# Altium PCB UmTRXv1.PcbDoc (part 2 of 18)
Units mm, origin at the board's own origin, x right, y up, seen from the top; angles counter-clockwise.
Board outline 172 x 113 mm, 6 copper layers (Top Layer, GND, MidLayer1, Mid-Layer 2, InternalPlane2, Bottom Layer); 766 components, 613 nets, 3008 pads, 1360 vias.
Unrouted connection lines stored in the file: 2.
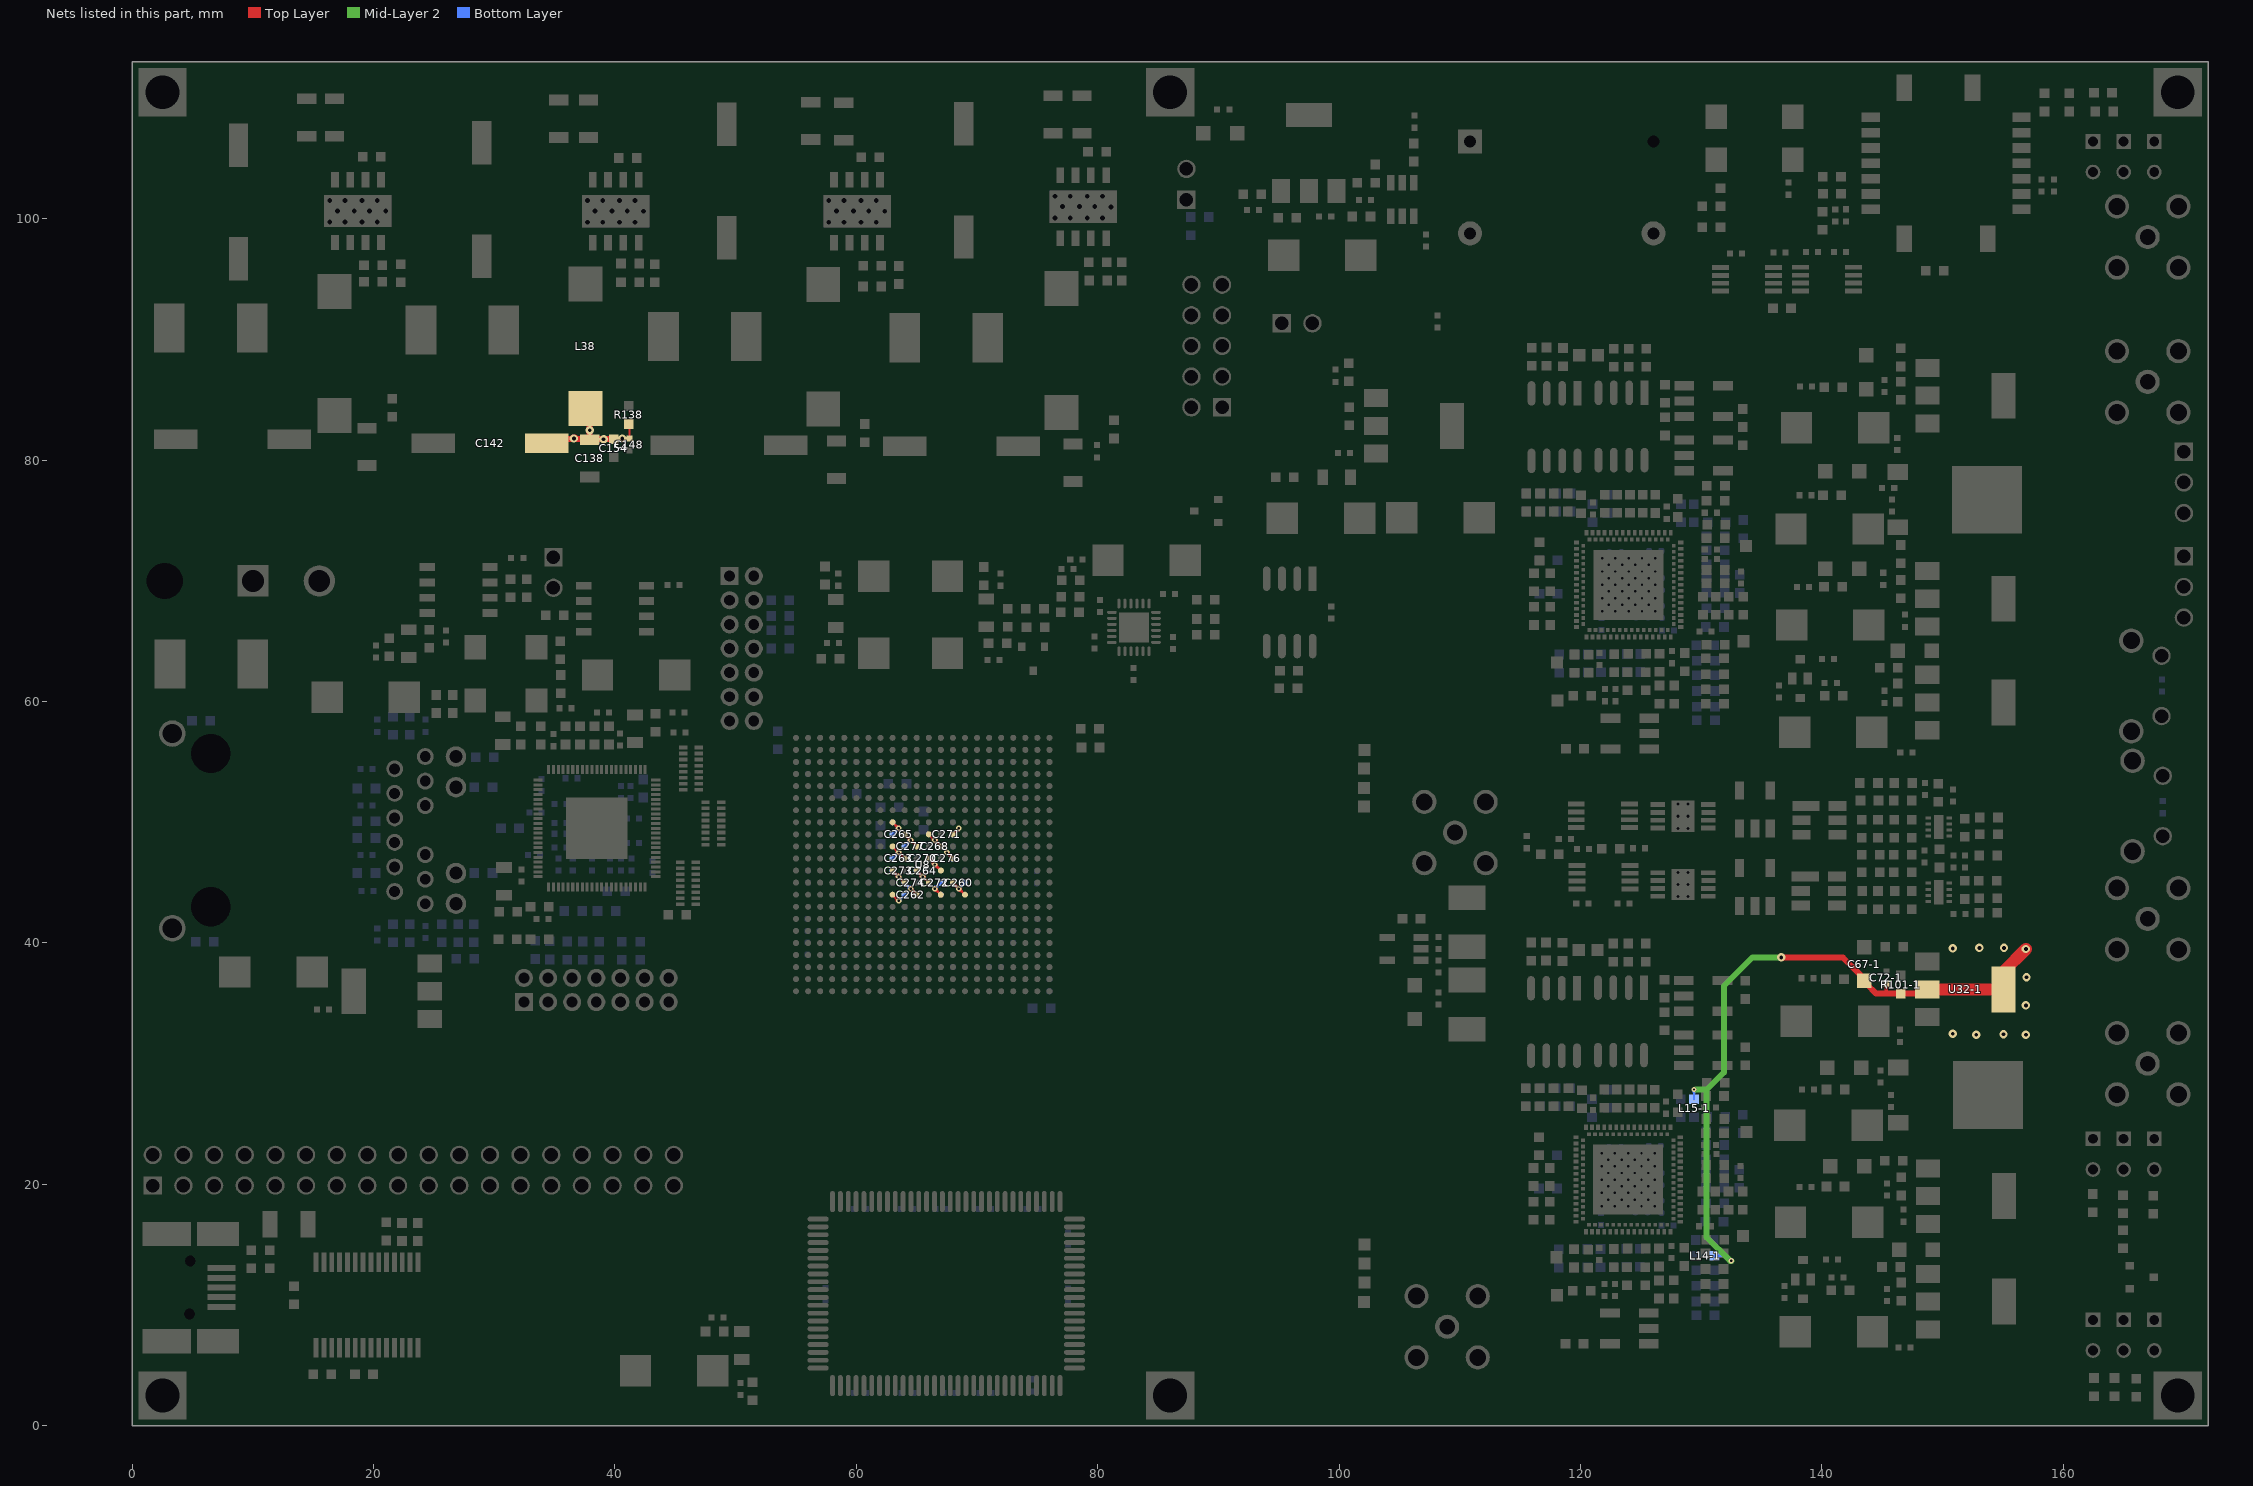
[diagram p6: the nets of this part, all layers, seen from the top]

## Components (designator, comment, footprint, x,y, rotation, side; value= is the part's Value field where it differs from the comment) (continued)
R125-2 "??" R0603-PHILLIPS 124.1,76.4 r270 top (schematic designator R125)
R126-1 "10" R0603-PHILLIPS 115.912,39.283 r90 top (schematic designator R126)
R126-2 "10" R0603-PHILLIPS 115.951,88.575 r90 top (schematic designator R126)
R127-1 "10" R0603-PHILLIPS 125.411,39.208 r90 top (schematic designator R127)
R127-2 "10" R0603-PHILLIPS 125.45,88.5 r90 top (schematic designator R127)
R128 "3k3" R0603-PHILLIPS 61.15,105.1 r0 top
R129 "4k7" R0603-PHILLIPS 19.85,105.15 r0 top
R130 "?" R0603-PHILLIPS 41.05,105.05 r0 top
R131 "4k7" R0603-PHILLIPS 61.3,94.4 r180 top
R132 "4k7" R0603-PHILLIPS 19.95,94.8 r180 top
R133 "4k7" R0603-PHILLIPS 41.25,94.75 r180 top
R134 "120" R0603-PHILLIPS 100.85,83.65 r90 top
R135 "360" R0603-PHILLIPS 100.8,87.3 r90 top
R136 "5k6" R0603-PHILLIPS 60.7,82.25 r90 top
R137 "5k1" R0603-PHILLIPS 21.55,84.35 r90 top
R138 "0" R0603-PHILLIPS 41.15,83.75 r90 top
R139 "430" R0603-PHILLIPS 143.351,43.556 r90 top
R140 "430" R0603-PHILLIPS 143.301,49.456 r90 top
R141 "12" R0603-PHILLIPS 144.651,43.556 r270 top
R142 "12" R0603-PHILLIPS 144.651,49.456 r270 top
R143 "6k8" R0603-PHILLIPS 153.8,43.7 r180 top
R144 "430" R0603-PHILLIPS 146.051,43.556 r270 top
R145 "6k8" R0603-PHILLIPS 153.85,49 r180 top
R146 "430" R0603-PHILLIPS 146.001,49.456 r270 top
R147 "10" R0603-PHILLIPS 146.7,47.3 r180 top
R148 "10" R0603-PHILLIPS 146.751,53.256 r180 top
R149 "330" R0603-PHILLIPS 53.7,64.4 r0 bottom
R150 "??" R0603-PHILLIPS 53.7,67.1 r180 bottom
R151 "??" R0603-PHILLIPS 53.7,65.9 r180 bottom
R152 "2k4" R0603-PHILLIPS 53.7,68.4 r180 bottom
R153 "1k" R0603-PHILLIPS 136.7,92.6 r0 top
R154-1 "270" R0603-PHILLIPS 116.111,17.808 r90 top (schematic designator R154)
R154-2 "270" R0603-PHILLIPS 116.15,67.1 r90 top (schematic designator R154)
R155-1 "62" R0603-PHILLIPS 117.461,17.808 r90 top (schematic designator R155)
R155-2 "62" R0603-PHILLIPS 117.5,67.1 r90 top (schematic designator R155)
R156-1 "62" R0603-PHILLIPS 130.111,18.658 r90 top (schematic designator R156)
R156-2 "62" R0603-PHILLIPS 130.15,67.95 r90 top (schematic designator R156)
R157-1 "270" R0603-PHILLIPS 132.261,18.658 r270 top (schematic designator R157)
R157-2 "270" R0603-PHILLIPS 132.3,67.95 r270 top (schematic designator R157)
R158-1 "270" R0603-PHILLIPS 116.111,20.608 r270 top (schematic designator R158)
R158-2 "270" R0603-PHILLIPS 116.15,69.9 r270 top (schematic designator R158)
R159-1 "62" R0603-PHILLIPS 117.461,20.608 r90 top (schematic designator R159)
R159-2 "62" R0603-PHILLIPS 117.5,69.9 r90 top (schematic designator R159)
R160 "0" R0603-PHILLIPS 88.95,66.85 r0 top
R161 "0" R0603-PHILLIPS 88.95,65.55 r180 top
R162 "330" R0603-PHILLIPS 160.5,109.65 r270 top
R163 "1k" R0603-PHILLIPS 23.65,16.05 r270 top
R164 "1k" R0603-PHILLIPS 21.05,16.1 r270 top
R165 "0" R0603-PHILLIPS 22.35,16.05 r90 top
R166 "0" R0603-PHILLIPS 13.4,10.8 r90 top
R167 "0" R0603-PHILLIPS 88.95,68.45 r0 top
R168 "1k2" R0603-PHILLIPS 79.95,105.575 r0 top
R169 "4k7" R0603-PHILLIPS 80.05,94.9 r180 top
R170 "4k7" R0603-PHILLIPS 81.35,82.55 r90 top
R171 "0" R0603-PHILLIPS 87.7,99.4 r90 bottom
R172 "??" R0603-PHILLIPS 88.45,100.15 r180 bottom
R173 "10k" R0603-PHILLIPS 95.85,62.55 r180 top
R174 "10k" R0603-PHILLIPS 95.8,61.1 r180 top
RA1 "33" YC248 46.3,54.45 r0 top
RA2 "33" YC248 48.15,49.9 r0 top
RA3 "33" YC248 46.05,44.95 r0 top
SW1 "TS-A1PV-130" KNOPKA 168.25,48.85 r90 top
SW2 "TS-A1PV-130" KNOPKA 168.15,58.8 r90 top
SW3 "PLS-3" PLT-3 170,72.04 r270 top
SW4 "PLS-3" PLT-3 170,80.7 r270 top
T1-1 "TC1-1-13MG2" AT224-1 124.061,8.058 r270 top (schematic designator T1)
T1-2 "TC1-1-13MG2" AT224-1 124.1,57.35 r270 top (schematic designator T1)
T2-1 "TC1-1-13MG2" AT224-1 130.161,31.108 r90 top (schematic designator T2)
T2-2 "TC1-1-13MG2" AT224-1 130.2,80.4 r90 top (schematic designator T2)
T3-1 "TC4-25+" AT224-1 130.161,35.608 r90 top (schematic designator T3)
T3-2 "TC4-25+" AT224-1 130.2,84.9 r90 top (schematic designator T3)
T4 "SBTC-2-20L" AT1030 134.45,44.65 r180 top
T5 "SBTC-2-20L" AT1030 134.45,51.05 r180 top
U1 "DAC121S101CIMK" SOT-23-6 105.239,101.6 r180 top
U2 "OHM4048052GG010020-26.0M" DIL14-20X13,2 108.45,96.3 r0 top
U3 "TCD4029-26.0M" TCXO7X5 137.6,108.456 r180 top
U4 "EB-230" EB-230 150.3,104.6 r180 top
U5 "Si5330K-A00226-GM" "QFN-24(4x4/0/5mm) with Pad" 83,66.15 r270 top
U6 "M25P16-VMW6TG" SOIC8 40.006,67.704 r0 top
U7 "24LC024SN" SOIC8 27.042,69.242 r0 top
U8 "XC6SLX75-2FGG484C" FBGA484 65.5,46.5 r180 top locked
U9 "ET1011C2-CI-DT" QFN-84(10X10/0/4MM)WITH_PAD 38.5,49.5 r270 top locked
U10 "FNETHE025" 7x5mm 30.95,62.3 r180 top
U11 "CY7C1354C-166AXI" QFP-10020X14/0.65] 67.45,10.95 r270 top
U12-1 "LMS6002D" DQFN120(9X9/0.5MM) 123.957,20.388 r270 top locked (schematic designator U12)
U12-2 "LMS6002D" DQFN120(9X9/0.5MM) 123.996,69.68 r270 top locked (schematic designator U12)
U13-1 "AD8130ARZ" SO-8 117.811,33.458 r270 top (schematic designator U13)
U13-2 "AD8130ARZ" SO-8 117.85,82.75 r270 top (schematic designator U13)
U14-1 "AD8130ARZ" SO-8 123.361,33.508 r270 top (schematic designator U14)
U14-2 "AD8130ARZ" SO-8 123.4,82.8 r270 top (schematic designator U14)
U15 "L5973AD" "SOIC8 - BackGND - 0.4mm dia" 60.06,100.637 r90 top
U16 "L5973AD" "SOIC8 - BackGND - 0.4mm dia" 18.7,100.65 r90 top
U17 "L5973AD" "SOIC8 - BackGND - 0.4mm dia" 40.06,100.637 r90 top
U18 "LD1117S" SOT-223-1 103.05,85.15 r270 top
U19 "TPS60403DBV" SOT-23-5[3.1x1.8/0.95] 105.398,39.512 r90 top
U20 "SN74LVC2T45DCT" SO-8-MICRO 121.901,45.456 r90 top
U21 "HMC435MS8G" MS8G 128.5,44.85 r270 top
U22 "SN74LVC2T45DCT" SO-8-MICRO 121.851,50.531 r90 top
U23 "HMC435MS8G" MS8G 128.5,50.5 r270 top
U24 "MGA-633P8" SLP2x2 149.7,44.2 r180 top
U25 "MGA-633P8" SLP2x2 149.701,49.606 r180 top
U26 "SN74LVC2T45DCT" SO-8-MICRO 133.808,94.996 r270 top
U27 "SN74LVC2T45DCT" SO-8-MICRO 140.421,95.011 r270 top
U28 "LD1117S" SOT-223-1 95.2,102.3 r0 top
U29-1 "LD1117DT33" to-252 146.35,29.685 r270 top (schematic designator U29)
U29-2 "LD1117DT33" to-252 146.3,79.02 r270 top (schematic designator U29)
U30-1 "LD1117S" SOT-223-1 148.79,12.581 r270 top (schematic designator U30)
U30-2 "LD1117S" SOT-223-1 148.74,62.226 r270 top (schematic designator U30)
U31-1 "LD1117S" SOT-223-1 148.79,21.327 r270 top (schematic designator U31)
U31-2 "LD1117S" SOT-223-1 148.74,70.826 r270 top (schematic designator U31)
U32-1 "LD1117S" SOT-223-1 148.74,38.456 r270 top (schematic designator U32)
U32-2 "LD1117S" SOT-223-1 148.75,87.65 r270 top (schematic designator U32)
U33 "FT232RL" SSOP-28(5.3x10/0.65) 19.45,10 r270 top
U34 "L5973AD" "SOIC8 - BackGND - 0.4mm dia" 78.8,101 r90 top
U35 "MAX6665ASA" SO-8 95.9,67.4 r270 top
X1 "BH2-14" BH2-14 38.45,36.1 r0 top
X2 "BH2-14" BH2-14 50.5,64.4 r270 top
X3 "USB B-M5-SMD" USB/SM0.8-6H5 -0.45,11.45 r180 top
X4 "0826-1XT-23-F" Bel0826-1XT-23F 3.325,49.35 r90 top locked
X5 "MF-2MRA" MF-2MRA 10,70 r0 top
X6 "MCX" RF-MCX 167,98.5 r0 top
X7 "MCX" RF-MCX 167,86.5 r0 top
X8 "MCX" RF-MCX 108.95,8.2 r0 top
X9 "MCX" RF-MCX 167,30 r0 top
X10 "MCX" RF-MCX 167,42 r0 top
X11 "MCX" RF-MCX 109.6,49.15 r0 top
X12 "PLD-36" PLD-36 1.7,19.9 r0 top
X12-1 "TST1" kp40x40 133.461,15.708 r270 top (schematic designator X12)
X12-2 "TST1" kp40x40 133.5,65 r270 top (schematic designator X12)
X13-1 "TST2" kp40x40 133.75,24.35 r90 top (schematic designator X13)
X13-2 "TST2" kp40x40 133.7,72.9 r90 top (schematic designator X13)
X14-1 "TST3" kp40x40 118.061,10.808 r90 top (schematic designator X14)
X14-2 "TST3" kp40x40 118.1,60.1 r90 top (schematic designator X14)
X15-1 "TST4" kp40x40 118.011,13.958 r90 top (schematic designator X15)
X15-2 "TST4" kp40x40 118.05,63.25 r90 top (schematic designator X15)
X16-1 "RX_I" kp40x40 119.861,39.408 r90 top (schematic designator X16)
X16-2 "RX_I" kp40x40 119.9,88.7 r90 top (schematic designator X16)
X17-1 "RX_Q" kp40x40 121.411,39.408 r90 top (schematic designator X17)
X17-2 "RX_Q" kp40x40 121.45,88.7 r90 top (schematic designator X17)
X18 "SEN1" kp40x40 102.049,10.25 r0 top
X19 "SCLK1" kp40x40 102.1,13.45 r0 top
X20 "MOSI1" kp40x40 102.1,11.85 r0 top
X21 "MISO1" kp40x40 102.1,15 r0 top
X22 "SEN2" kp40x40 102.05,51.3 r0 top
X23 "SCLK2" kp40x40 102.05,54.45 r0 top
X24 "MOSI2" kp40x40 102.05,52.85 r0 top
X25 "MISO2" kp40x40 102.1,56 r0 top
X26 "BH-10" BH-10 88.98,89.47 r90 top
X27 "FAN1" WF-2 87.35,101.6 r90 top
X28 "FAN2" WF-2 95.25,91.35 r0 top
Z1-1 "NFM3DPC223R1H3" NFM3DP 138.44,12.131 r270 top (schematic designator Z1)
Z1-2 "NFM3DPC223R1H3" NFM3DP 138.2,61.9 r270 top (schematic designator Z1)
Z2 "SAW UpLink" DCC6C_L 139.751,44.306 r180 top
Z3 "SAW UpLink" DCC6C_L 139.801,50.156 r180 top

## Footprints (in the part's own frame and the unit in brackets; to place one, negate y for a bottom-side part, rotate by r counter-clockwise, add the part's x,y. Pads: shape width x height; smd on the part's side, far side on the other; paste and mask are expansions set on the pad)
7x5mm [mm]
  rect 1.8x2 smd: 1(-2.54,-2.2) 2(2.54,-2.2) 3(2.54,2.2) 4(-2.54,2.2)
  silkscreen extent -3.7,-2.7 3.7,2.7, body extent -3.6,-2.6 3.6,2.6, height 1.55
AT224-1 [mm] "MiniCircuits TC"
  rect 0.76x1.65 smd: 1(-1.27,1.6) 2(0,1.6) 3(1.27,1.6) 4(1.27,-1.6) 6(-1.27,-1.6)
  silkscreen extent -2.2,-1.8 2.2,1.8, body extent -2.1,-1.9 2.1,1.9, height 3.61
AT1030 [mm] "MiniCircuits DBTC"
  rect 0.76x1.5 smd: 1(-1.27,1.575) 2(0,1.575) 3(1.27,1.575) 4(1.27,-1.575) 6(-1.27,-1.575)
  silkscreen extent -2.2,-1.8 2.2,1.8, body extent -2,-1.7 2,1.7, height 3
Bel0826-1XT-23F [mm]
  round 0 hole 3.25 unplated mask+1.7: 0(-6.35,-3.175) 0(6.35,-3.175)
  round 1.4 hole 0.9: 1(-5.08,-18.415) 2(-3.048,-18.415) 3(-1.016,-18.415) 4(1.016,-18.415) 5(3.048,-18.415) 6(5.08,-18.415) 7(-6.096,-20.955) 8(-4.064,-20.955) 9(-2.032,-20.955) 10(2.032,-20.955) 11(4.064,-20.955) 12(6.096,-20.955)
  round 1.7 hole 1.1: 13(-6.096,-23.495) 14(-3.556,-23.495) 15(3.556,-23.495) 16(6.096,-23.495)
  round 2.2 hole 1.6: 17(-8.128,0) 17(8.001,0)
  silkscreen extent -8.51,-26.16 8.51,5.46, body extent -9.94,-25.4 9.93,7.62, height 14.9
BH2-14 [mm] "Molex  87831-1420"
  rect 1.5x1.5 hole 0.9: 1(-6,-1)
  round 1.5 hole 0.9: 2(-6,1) 3(-4,-1) 4(-4,1) 5(-2,-1) 6(-2,1) 7(0,-1) 8(0,1) 9(2,-1) 10(2,1) 11(4,-1) 12(4,1) 13(6,-1) 14(6,1)
  silkscreen extent -11.1,-2.9 11.1,2.9, body extent -8.32,-3.15 8.33,3.15, height 6.45
BH-10 [mil]
  rect 60x60 hole 44: 1(-200,-51.97)
  round 60 hole 44: 2(-200,48.03) 3(-100,-51.97) 4(-100,48.03) 5(0,-51.97) 6(0,48.03) 7(100,-51.97) 8(100,48.03) 9(200,-51.97) 10(200,48.03)
  silkscreen extent -400,-179 402,181, body extent -390,-165 388,181, height 366
C0402-Cirq [mm]
  rrect70% 0.5x0.5 smd: 1(-0.5,0) 2(0.5,0)
  silkscreen extent -0.9,-0.4 0.9,0.4, body extent -0.5,-0.3 0.5,0.3, height 0.2
C0402-cirq [mm]
  rrect70% 0.5x0.5 smd: 1(-0.5,0) 2(0.5,0)
  silkscreen extent -0.9,-0.4 0.9,0.4, body extent -0.5,-0.3 0.5,0.3, height 0.2
C0402-Phillips [mm]
  rect 0.5x0.5 smd: 1(-0.5,0) 2(0.5,0)
  silkscreen extent -0.9,-0.4 0.9,0.4, body extent -0.57,-0.3 0.57,0.3, height 0.55
C0603-PHILLIPS [mm]
  rect 0.8x0.8 smd: 1(-0.75,0) 2(0.75,0)
  silkscreen extent 0,-0.38 0,0.38, body extent -0.86,-0.45 0.85,0.45, height 0.9
C0603-Phillips [mm]
  rect 0.8x0.8 smd: 1(-0.75,0) 2(0.75,0)
  silkscreen extent 0,-0.38 0,0.38, body extent -0.86,-0.45 0.85,0.45, height 0.9
C0805-Phillips [mm]
  rect 0.9x1.3 smd: 1(-1.15,0) 2(1.15,0)
  silkscreen extent -1.91,-0.92 1.91,0.92, body extent -1.32,-0.69 1.23,0.67, height 0.5
c1206 [mm]
  rect 0.9x1.6 smd: 1(-1.55,0) 2(1.55,0)
  silkscreen extent -2.12,-1.12 2.12,1.12, body extent -1.64,-0.89 1.63,0.86, height 0.9
CA3216 [mm] "Конденсатор эл-лит. тип А  по Fillips"
  rect 1.2x1.2 smd: 1(-1.4,0) 2(1.4,0)
  silkscreen extent -2,-1.1 2.2,1.1, body extent -2.35,-0.9 2.45,0.9, height 1.8
CASE-G [mm] "Allu cylinder"
  rect 3.6x1.6 smd: 1(4.7,0) 2(-4.7,0)
  silkscreen extent -5.3,-5.33 5.3,5.33, body extent -5.8,-5.15 5.8,5.15, height 10.21
CB3528 [mm] "Конденсатор тип B по Fillips"
  rect 1.25x2.2 smd: 1(-1.575,0) 2(1.575,0)
  silkscreen extent -2.3,-1.5 2.5,1.5, body extent -1.79,-1.54 1.8,1.54, height 1
cd7343 [mm]
  rect 2.6x2.6 smd: 1(3.2,0) 2(-3.2,0)
  silkscreen extent -3.7,-2.1 3.7,2.2, body extent -3.51,-2.04 3.5,2.03, height 3.1
CR1812 [mil]
  rect 80x120 smd: 1(-80,0) 2(80,0)
  silkscreen extent -130,-70 130,70, body extent -93,-67 93,67, height 61
DCC6C_L [mm] "SAW"
  rect 2.25x0.8 smd mask+0.1: 1(1.125,-1.2)
  rect 1.5x0.8 smd mask+0.1: 2(1.5,0) 3(1.5,1.2)
  rect 1.5x0.8 smd: 4(-1.5,1.2) 5(-1.5,0) 6(-1.5,-1.2)
  silkscreen extent -2,-2.4 2.3,2, body extent -1.5,-1.5 1.5,1.5, height 1.1
DIL14-20X13,2 [mm] "VCXO"
  rect 2x2 hole 1: 1(2.4,10.1)
  round 0 / inner round 0 / far side round 2 hole 1: 7(17.6,10.1)
  round 2 hole 1: 8(17.6,2.5) 14(2.4,2.5)
  Multi-Layer pour cut-out: 16.8,2.9 17.2,3.3 18,3.3 18.4,2.9 18.4,2.1 18,1.7 17.2,1.7 16.8,2.1
  Multi-Layer pour cut-out: 1.6,2.9 2,3.3 2.8,3.3 3.2,2.9 3.2,2.1 2.8,1.7 2,1.7 1.6,2.1
  Multi-Layer pour cut-out: 1.6,10.5 2,10.9 2.8,10.9 3.2,10.5 3.2,9.7 2.8,9.3 2,9.3 1.6,9.7
  Multi-Layer pour cut-out: 16.8,10.5 17.2,10.9 18,10.9 18.4,10.5 18.4,9.7 18,9.3 17.2,9.3 16.8,9.7
  silkscreen extent -0.25,-0.38 20.32,12.95, body extent 0.07,0.1 20.07,12.7, height 8.2
DQFN120(9X9/0.5MM) [mm] "LMS6002"
  round 0.5 hole 0.2 paste-0.4: 0(-2.2,1.1) 0(-2.2,2.2) 0(-2.2,0) 0(-2.2,-2.2) 0(-2.2,-1.1) 0(-1.65,1.65) 0(-1.65,-0.55) 0(-1.65,0.55) 0(-1.65,-1.65) 0(-1.1,2.2) 0(-1.1,1.1) 0(-1.1,0) 0(-1.1,-1.1) 0(-1.1,-2.2) 0(-0.55,1.65) 0(-0.55,0.55) 0(-0.55,-0.55) 0(-0.55,-1.65) 0(0,2.2) 0(0,1.1) 0(0,0) 0(0,-1.1) 0(0,-2.2) 0(0.55,1.65) 0(0.55,0.55) 0(0.55,-0.55) 0(0.55,-1.65) 0(1.1,2.2) 0(1.1,1.1) 0(1.1,0) 0(1.1,-1.1) 0(1.1,-2.2) 0(1.65,1.65) 0(1.65,-0.55) 0(1.65,0.55) 0(1.65,-1.65) 0(2.2,1.1) 0(2.2,2.2) 0(2.2,0) 0(2.2,-2.2) 0(2.2,-1.1)
  rect 5.8x5.8 smd paste-3: 0(0,0)
  rect 0.3x0.45 smd mask+0.05: 1(-3.5,-4.325) 3(-3,-4.325) 5(-2.5,-4.325) 7(-2,-4.325) 9(-1.5,-4.325) 11(-1,-4.325) 13(-0.5,-4.325) 15(0,-4.325) 17(0.5,-4.325) 19(1,-4.325) 21(1.5,-4.325) 23(2,-4.325) 25(2.5,-4.325) 27(3,-4.325) 29(3.5,-4.325) 59(3.5,4.325) 61(3,4.325) 63(2.5,4.325) 65(2,4.325) 67(1.5,4.325) 69(1,4.325) 71(0.5,4.325) 73(0,4.325) 75(-0.5,4.325) 77(-1,4.325) 79(-1.5,4.325) 81(-2,4.325) 83(-2.5,4.325) 85(-3,4.325) 87(-3.5,4.325)
  rect 0.3x0.3 smd mask+0.05: 2(-3.25,-3.75) 4(-2.75,-3.75) 6(-2.25,-3.75) 8(-1.75,-3.75) 10(-1.25,-3.75) 12(-0.75,-3.75) 14(-0.25,-3.75) 16(0.25,-3.75) 18(0.75,-3.75) 20(1.25,-3.75) 22(1.75,-3.75) 24(2.25,-3.75) 26(2.75,-3.75) 28(3.25,-3.75) 31(3.75,-3.25) 33(3.75,-2.75) 35(3.75,-2.25) 37(3.75,-1.75) 39(3.75,-1.25) 41(3.75,-0.75) 43(3.75,-0.25) 45(3.75,0.25) 47(3.75,0.75) 49(3.75,1.25) 51(3.75,1.75) 53(3.75,2.25) 55(3.75,2.75) 57(3.75,3.25) 60(3.25,3.75) 62(2.75,3.75) 64(2.25,3.75) 66(1.75,3.75) 68(1.25,3.75) 70(0.75,3.75) 72(0.25,3.75) 74(-0.25,3.75) 76(-0.75,3.75) 78(-1.25,3.75) 80(-1.75,3.75) 82(-2.25,3.75) 84(-2.75,3.75) 86(-3.25,3.75) 89(-3.75,3.25) 91(-3.75,2.75) 93(-3.75,2.25) 95(-3.75,1.75) 97(-3.75,1.25) 99(-3.75,0.75) 101(-3.75,0.25) 103(-3.75,-0.25) 105(-3.75,-0.75) 107(-3.75,-1.25) 109(-3.75,-1.75) 111(-3.75,-2.25) 113(-3.75,-2.75) 115(-3.75,-3.25)
  rect 0.45x0.3 smd mask+0.05: 30(4.325,-3.5) 32(4.325,-3) 34(4.325,-2.5) 36(4.325,-2) 38(4.325,-1.5) 40(4.325,-1) 42(4.325,-0.5) 44(4.325,0) 46(4.325,0.5) 48(4.325,1) 50(4.325,1.5) 52(4.325,2) 54(4.325,2.5) 56(4.325,3) 58(4.325,3.5) 88(-4.325,3.5) 90(-4.325,3) 92(-4.325,2.5) 94(-4.325,2) 96(-4.325,1.5) 98(-4.325,1) 100(-4.325,0.5) 102(-4.325,0) 104(-4.325,-0.5) 106(-4.325,-1) 108(-4.325,-1.5) 110(-4.325,-2) 112(-4.325,-2.5) 114(-4.325,-3) 116(-4.325,-3.5)
  silkscreen extent -4.8,-4.8 4.8,4.8, body extent -4.5,-4.5 4.5,4.5, height 0.85
DS3316 [mm] "Coilcraft"
  rect 2.9x2.8 smd: 1(-5.15,0) 2(5.15,0)
  silkscreen extent -5.2,-4.8 5.2,4.8, body extent -4.9,-4.9 5.1,5.1, height 2.8
EB-230 [mm]
  rect 1.5x0.8 smd mask+0.077: 1(-6.25,3.81) 2(-6.25,2.54) 3(-6.25,1.27) 4(-6.25,0) 5(-6.25,-1.27) 6(-6.25,-2.54) 7(-6.25,-3.81) 10(6.25,-3.81) 11(6.25,-2.54) 12(6.25,-1.27) 13(6.25,0) 14(6.25,1.27) 15(6.25,2.54) 16(6.25,3.81)
  rect 1.3x2.2 smd mask+0.077: 8(-2.19,-6.25) 9(3.46,-6.25) 17(3.46,6.25) 18(-3.46,6.25)
  silkscreen extent -6.4,-6.4 6.4,6.4, body extent -6.25,-6.25 6,6.25, height 2.9
FBGA484 [mm] "BGA, 484-Leads, Body 23x23mm, Pitch 1mm"
  round 0.5 smd: A1(-10.5,10.5) A2(-9.5,10.5) A3(-8.5,10.5) A4(-7.5,10.5) A5(-6.5,10.5) A6(-5.5,10.5) A7(-4.5,10.5) A8(-3.5,10.5) A9(-2.5,10.5) A10(-1.5,10.5) A11(-0.5,10.5) A12(0.5,10.5) A13(1.5,10.5) A14(2.5,10.5) A15(3.5,10.5) A16(4.5,10.5) A17(5.5,10.5) A18(6.5,10.5) A19(7.5,10.5) A20(8.5,10.5) A21(9.5,10.5) A22(10.5,10.5) AA1(-10.5,-9.5) AA2(-9.5,-9.5) AA3(-8.5,-9.5) AA4(-7.5,-9.5) AA5(-6.5,-9.5) AA6(-5.5,-9.5) AA7(-4.5,-9.5) AA8(-3.5,-9.5) AA9(-2.5,-9.5) AA10(-1.5,-9.5) AA11(-0.5,-9.5) AA12(0.5,-9.5) AA13(1.5,-9.5) AA14(2.5,-9.5) AA15(3.5,-9.5) AA16(4.5,-9.5) AA17(5.5,-9.5) AA18(6.5,-9.5) AA19(7.5,-9.5) AA20(8.5,-9.5) AA21(9.5,-9.5) AA22(10.5,-9.5) AB1(-10.5,-10.5) AB2(-9.5,-10.5) AB3(-8.5,-10.5) AB4(-7.5,-10.5) AB5(-6.5,-10.5) AB6(-5.5,-10.5) AB7(-4.5,-10.5) AB8(-3.5,-10.5) AB9(-2.5,-10.5) AB10(-1.5,-10.5) AB11(-0.5,-10.5) AB12(0.5,-10.5) AB13(1.5,-10.5) AB14(2.5,-10.5) AB15(3.5,-10.5) AB16(4.5,-10.5) AB17(5.5,-10.5) AB18(6.5,-10.5) AB19(7.5,-10.5) AB20(8.5,-10.5) AB21(9.5,-10.5) AB22(10.5,-10.5) B1(-10.5,9.5) B2(-9.5,9.5) B3(-8.5,9.5) B4(-7.5,9.5) B5(-6.5,9.5) B6(-5.5,9.5) B7(-4.5,9.5) B8(-3.5,9.5) B9(-2.5,9.5) B10(-1.5,9.5) B11(-0.5,9.5) B12(0.5,9.5) B13(1.5,9.5) B14(2.5,9.5) B15(3.5,9.5) B16(4.5,9.5) B17(5.5,9.5) B18(6.5,9.5) B19(7.5,9.5) B20(8.5,9.5) B21(9.5,9.5) B22(10.5,9.5) C1(-10.5,8.5) C2(-9.5,8.5) C3(-8.5,8.5) C4(-7.5,8.5) C5(-6.5,8.5) C6(-5.5,8.5) C7(-4.5,8.5) C8(-3.5,8.5) C9(-2.5,8.5) C10(-1.5,8.5) C11(-0.5,8.5) C12(0.5,8.5) C13(1.5,8.5) C14(2.5,8.5) C15(3.5,8.5) C16(4.5,8.5) C17(5.5,8.5) C18(6.5,8.5) C19(7.5,8.5) C20(8.5,8.5) C21(9.5,8.5) C22(10.5,8.5) D1(-10.5,7.5) D2(-9.5,7.5) D3(-8.5,7.5) D4(-7.5,7.5) D5(-6.5,7.5) D6(-5.5,7.5) D7(-4.5,7.5) D8(-3.5,7.5) D9(-2.5,7.5) D10(-1.5,7.5) D11(-0.5,7.5) D12(0.5,7.5) D13(1.5,7.5) D14(2.5,7.5) D15(3.5,7.5) D16(4.5,7.5) D17(5.5,7.5) D18(6.5,7.5) D19(7.5,7.5) D20(8.5,7.5) D21(9.5,7.5) D22(10.5,7.5) E1(-10.5,6.5) E2(-9.5,6.5) E3(-8.5,6.5) E4(-7.5,6.5) E5(-6.5,6.5) E6(-5.5,6.5) E7(-4.5,6.5) E8(-3.5,6.5) E9(-2.5,6.5) E10(-1.5,6.5) E11(-0.5,6.5) E12(0.5,6.5) E13(1.5,6.5) E14(2.5,6.5) E15(3.5,6.5) E16(4.5,6.5) E17(5.5,6.5) E18(6.5,6.5) E19(7.5,6.5) E20(8.5,6.5) E21(9.5,6.5) E22(10.5,6.5) F1(-10.5,5.5) F2(-9.5,5.5) F3(-8.5,5.5) F4(-7.5,5.5) F5(-6.5,5.5) F6(-5.5,5.5) F7(-4.5,5.5) F8(-3.5,5.5) F9(-2.5,5.5) F10(-1.5,5.5) F11(-0.5,5.5) F12(0.5,5.5) F13(1.5,5.5) F14(2.5,5.5) F15(3.5,5.5) F16(4.5,5.5) F17(5.5,5.5) F18(6.5,5.5) F19(7.5,5.5) F20(8.5,5.5) F21(9.5,5.5) F22(10.5,5.5) G1(-10.5,4.5) G2(-9.5,4.5) G3(-8.5,4.5) G4(-7.5,4.5) G5(-6.5,4.5) G6(-5.5,4.5) G7(-4.5,4.5) G8(-3.5,4.5) G9(-2.5,4.5) G10(-1.5,4.5) G11(-0.5,4.5) G12(0.5,4.5) G13(1.5,4.5) G14(2.5,4.5) G15(3.5,4.5) G16(4.5,4.5) G17(5.5,4.5) G18(6.5,4.5) G19(7.5,4.5) G20(8.5,4.5) G21(9.5,4.5) G22(10.5,4.5) H1(-10.5,3.5) H2(-9.5,3.5) H3(-8.5,3.5) H4(-7.5,3.5) H5(-6.5,3.5) H6(-5.5,3.5) H7(-4.5,3.5) H8(-3.5,3.5) H9(-2.5,3.5) H10(-1.5,3.5) H11(-0.5,3.5) H12(0.5,3.5) H13(1.5,3.5) H14(2.5,3.5) H15(3.5,3.5) H16(4.5,3.5) H17(5.5,3.5) H18(6.5,3.5) H19(7.5,3.5) H20(8.5,3.5) H21(9.5,3.5) H22(10.5,3.5) J1(-10.5,2.5) J2(-9.5,2.5) J3(-8.5,2.5) J4(-7.5,2.5) J5(-6.5,2.5) J6(-5.5,2.5) J7(-4.5,2.5) J8(-3.5,2.5) J9(-2.5,2.5) J10(-1.5,2.5) J11(-0.5,2.5) J12(0.5,2.5) J13(1.5,2.5) J14(2.5,2.5) J15(3.5,2.5) J16(4.5,2.5) J17(5.5,2.5) J18(6.5,2.5) J19(7.5,2.5) J20(8.5,2.5) J21(9.5,2.5) J22(10.5,2.5) K1(-10.5,1.5) K2(-9.5,1.5) K3(-8.5,1.5) K4(-7.5,1.5) K5(-6.5,1.5) K6(-5.5,1.5) K7(-4.5,1.5) K8(-3.5,1.5) K9(-2.5,1.5) K10(-1.5,1.5) K11(-0.5,1.5) K12(0.5,1.5) K13(1.5,1.5) K14(2.5,1.5) K15(3.5,1.5) K16(4.5,1.5) K17(5.5,1.5) K18(6.5,1.5) K19(7.5,1.5) K20(8.5,1.5) K21(9.5,1.5) K22(10.5,1.5) L1(-10.5,0.5) L2(-9.5,0.5) L3(-8.5,0.5) L4(-7.5,0.5) L5(-6.5,0.5) L6(-5.5,0.5) L7(-4.5,0.5) L8(-3.5,0.5) L9(-2.5,0.5) L10(-1.5,0.5) L11(-0.5,0.5) L12(0.5,0.5) L13(1.5,0.5) L14(2.5,0.5) L15(3.5,0.5) L16(4.5,0.5) L17(5.5,0.5) L18(6.5,0.5) L19(7.5,0.5) L20(8.5,0.5) L21(9.5,0.5) L22(10.5,0.5) M1(-10.5,-0.5) M2(-9.5,-0.5) M3(-8.5,-0.5) M4(-7.5,-0.5) M5(-6.5,-0.5) M6(-5.5,-0.5) M7(-4.5,-0.5) M8(-3.5,-0.5) M9(-2.5,-0.5) M10(-1.5,-0.5) M11(-0.5,-0.5) M12(0.5,-0.5) M13(1.5,-0.5) M14(2.5,-0.5) M15(3.5,-0.5) M16(4.5,-0.5) M17(5.5,-0.5) M18(6.5,-0.5) M19(7.5,-0.5) M20(8.5,-0.5) M21(9.5,-0.5) M22(10.5,-0.5) N1(-10.5,-1.5) N2(-9.5,-1.5) N3(-8.5,-1.5) N4(-7.5,-1.5) N5(-6.5,-1.5) N6(-5.5,-1.5) N7(-4.5,-1.5) N8(-3.5,-1.5) N9(-2.5,-1.5) N10(-1.5,-1.5) N11(-0.5,-1.5) N12(0.5,-1.5) N13(1.5,-1.5) N14(2.5,-1.5) N15(3.5,-1.5) N16(4.5,-1.5) N17(5.5,-1.5) N18(6.5,-1.5) N19(7.5,-1.5) N20(8.5,-1.5) N21(9.5,-1.5) N22(10.5,-1.5) P1(-10.5,-2.5) P2(-9.5,-2.5) P3(-8.5,-2.5) P4(-7.5,-2.5) P5(-6.5,-2.5) P6(-5.5,-2.5) P7(-4.5,-2.5) P8(-3.5,-2.5) P9(-2.5,-2.5) P10(-1.5,-2.5) P11(-0.5,-2.5) P12(0.5,-2.5) P13(1.5,-2.5) P14(2.5,-2.5) P15(3.5,-2.5) P16(4.5,-2.5) P17(5.5,-2.5) P18(6.5,-2.5) P19(7.5,-2.5) P20(8.5,-2.5) P21(9.5,-2.5) P22(10.5,-2.5) R1(-10.5,-3.5) R2(-9.5,-3.5) R3(-8.5,-3.5) R4(-7.5,-3.5) R5(-6.5,-3.5) R6(-5.5,-3.5) R7(-4.5,-3.5) R8(-3.5,-3.5) R9(-2.5,-3.5) R10(-1.5,-3.5) R11(-0.5,-3.5) R12(0.5,-3.5) R13(1.5,-3.5) R14(2.5,-3.5) R15(3.5,-3.5) R16(4.5,-3.5) R17(5.5,-3.5) R18(6.5,-3.5) R19(7.5,-3.5) R20(8.5,-3.5) R21(9.5,-3.5) R22(10.5,-3.5) T1(-10.5,-4.5) T2(-9.5,-4.5) T3(-8.5,-4.5) T4(-7.5,-4.5) T5(-6.5,-4.5) T6(-5.5,-4.5) T7(-4.5,-4.5) T8(-3.5,-4.5) T9(-2.5,-4.5) T10(-1.5,-4.5) T11(-0.5,-4.5) T12(0.5,-4.5) T13(1.5,-4.5) T14(2.5,-4.5) T15(3.5,-4.5) T16(4.5,-4.5) T17(5.5,-4.5) T18(6.5,-4.5) T19(7.5,-4.5) T20(8.5,-4.5) T21(9.5,-4.5) T22(10.5,-4.5) U1(-10.5,-5.5) U2(-9.5,-5.5) U3(-8.5,-5.5) U4(-7.5,-5.5) U5(-6.5,-5.5) U6(-5.5,-5.5) U7(-4.5,-5.5) U8(-3.5,-5.5) U9(-2.5,-5.5) U10(-1.5,-5.5) U11(-0.5,-5.5) U12(0.5,-5.5) U13(1.5,-5.5) U14(2.5,-5.5) U15(3.5,-5.5) U16(4.5,-5.5) U17(5.5,-5.5) U18(6.5,-5.5) U19(7.5,-5.5) U20(8.5,-5.5) U21(9.5,-5.5) U22(10.5,-5.5) V1(-10.5,-6.5) V2(-9.5,-6.5) V3(-8.5,-6.5) V4(-7.5,-6.5) V5(-6.5,-6.5) V6(-5.5,-6.5) V7(-4.5,-6.5) V8(-3.5,-6.5) V9(-2.5,-6.5) V10(-1.5,-6.5) V11(-0.5,-6.5) V12(0.5,-6.5) V13(1.5,-6.5) V14(2.5,-6.5) V15(3.5,-6.5) V16(4.5,-6.5) V17(5.5,-6.5) V18(6.5,-6.5) V19(7.5,-6.5) V20(8.5,-6.5) V21(9.5,-6.5) V22(10.5,-6.5) W1(-10.5,-7.5) W2(-9.5,-7.5) W3(-8.5,-7.5) W4(-7.5,-7.5) W5(-6.5,-7.5) W6(-5.5,-7.5) W7(-4.5,-7.5) W8(-3.5,-7.5) W9(-2.5,-7.5) W10(-1.5,-7.5) W11(-0.5,-7.5) W12(0.5,-7.5) W13(1.5,-7.5) W14(2.5,-7.5) W15(3.5,-7.5) W16(4.5,-7.5) W17(5.5,-7.5) W18(6.5,-7.5) W19(7.5,-7.5) W20(8.5,-7.5) W21(9.5,-7.5) W22(10.5,-7.5) Y1(-10.5,-8.5) Y2(-9.5,-8.5) Y3(-8.5,-8.5) Y4(-7.5,-8.5) Y5(-6.5,-8.5) Y6(-5.5,-8.5) Y7(-4.5,-8.5) Y8(-3.5,-8.5) Y9(-2.5,-8.5) Y10(-1.5,-8.5) Y11(-0.5,-8.5) Y12(0.5,-8.5) Y13(1.5,-8.5) Y14(2.5,-8.5) Y15(3.5,-8.5) Y16(4.5,-8.5) Y17(5.5,-8.5) Y18(6.5,-8.5) Y19(7.5,-8.5) Y20(8.5,-8.5) Y21(9.5,-8.5) Y22(10.5,-8.5)
  silkscreen extent -12.27,-11.5 11.5,11.5, body extent -11.5,-11.5 11.5,11.5, height 3.5
KNOPKA [mil]
  round 60 hole 44: 1(0,0) 2(196.85,0)
  round 80 hole 56: 3(-49.21,98.43) 4(246.07,98.43)
  silkscreen extent -52,-115 248,175, body extent -62,-153 259,154, height 280
kp40x40 [mm]
  rect 1x1 smd: 1(0,0)
L-7104SA/3 [mil] "L-7104SA/3"
  rect 48x48 hole 32: 1(-50,-175.2) 2(-50,-275.2) 3(-50,-375.2)
  round 48 hole 32: 4(50,-375.2) 5(50,-275.2) 6(50,-175.2)
  silkscreen extent -104,-455 104,0, body extent -100,-451 100,103, height 600
LED-0603y [mm] "жёлтый"
  rect 0.8x0.8 smd: 1(-0.75,0) 2(0.75,0)
  silkscreen extent -1.45,-0.6 0.8,0.6, body extent -1.09,-0.4 0.92,0.4, height 0.8
MF-2MRA [mm]
  round 0 hole 3 unplated mask+1.6: 0(-7.3,0)
  rect 2.6x2.6 hole 1.8: 1(0,0)
  round 2.6 hole 1.8: 2(5.5,0)
  silkscreen extent -14,-2.8 -1,2.8, body extent -13.86,-3.13 6.08,2.67, height 11.4
MS8G [mm] "Hittite 8 Leg Grounded microSOIC"
  round 0.5 hole 0.254 paste-0.125 mask-0.125: 0(-1,-0.4) 0(-1,0.4) 0(0,0.4) 0(0,-0.4) 0(1,-0.4) 0(1,0.4)
  rect 2.6x1.9 smd paste-1.5: 0(0,0)
  rect 0.4x1.2 smd mask+0.075: 1(-0.975,-2.1) 2(-0.325,-2.1) 3(0.325,-2.1) 4(0.975,-2.1) 5(0.975,2.1) 6(0.325,2.1) 7(-0.325,2.11) 8(-0.975,2.1)
  silkscreen extent -1.65,-1.65 1.65,1.65, body extent -1.5,-2.45 1.5,2.45, height 0.85
NFM3DP [mm] "Фильтр электромагнитных помех"
  rect 0.7x0.8 smd: 1(-1.6,0) 3(1.6,0)
  rect 1x0.7 smd: 2(0,0.65) 2(0,-0.65)
  silkscreen extent -2,-1.3 2.1,1.3, body extent -1.6,-0.7 1.6,0.7, height 0.55
PLD-36 [mil]
  rect 60x60 hole 44: 1(0,0)
  round 60 hole 44: 2(0,100) 3(100,0) 4(100,100) 5(200,0) 6(200,100) 7(300,0) 8(300,100) 9(400,0) 10(400,100) 11(500,0) 12(500,100) 13(600,0) 14(600,100) 15(700,0) 16(700,100) 17(800,0) 18(800,100) 19(900,0) 20(900,100) 21(1000,0) 22(1000,100) 23(1100,0) 24(1100,100) 25(1200,0) 26(1200,100) 27(1300,0) 28(1300,100) 29(1400,0) 30(1400,100) 31(1500,0) 32(1500,100) 33(1600,0) 34(1600,100) 35(1700,0) 36(1700,100)
  silkscreen extent -50,-50 1750,150, body extent -50,-50 1750,150, height 398
PLT-2 [mil]
  rect 60x60 / inner round 60 / far side rect 60x60 hole 44: 1(-50,0)
  round 60 hole 44: 2(50,0)
  silkscreen extent -100,-50 100,50, body extent -90,-38 87,40, height 276
PLT-3 [mil]
  rect 60x60 hole 44: 1(0,0)
  round 60 hole 44: 2(100,0) 3(200,0)
  silkscreen extent -50,-50 250,50, body extent -50,-52 250,46, height 410
"QFN-24(4x4/0/5mm) with Pad" [mm] "PQFN"
  rect 2.5x2.5 smd paste-2: 0(0,0)
  oval 0.8x0.25 smd mask+0.075: 1(-1.975,1.25) 2(-1.975,0.75) 3(-1.975,0.25) 4(-1.975,-0.25) 5(-1.975,-0.75) 6(-1.975,-1.25) 13(1.975,-1.25) 14(1.975,-0.75) 15(1.975,-0.25) 16(1.975,0.25) 17(1.975,0.75) 18(1.975,1.25)
  oval 0.25x0.8 smd mask+0.075: 7(-1.25,-1.825) 8(-0.75,-1.825) 9(-0.25,-1.825) 10(0.25,-1.825) 11(0.75,-1.825) 12(1.25,-1.825) 19(1.25,1.825) 20(0.75,1.825) 21(0.25,1.825) 22(-0.25,1.825) 23(-0.75,1.825) 24(-1.25,1.825)
  silkscreen extent -2.97,-2.1 2.1,2.1, body extent -2.1,-1.92 2.1,1.92, height 0.9
QFN-84(10X10/0/4MM)WITH_PAD [mm] "QFN, 84-Leads, Body 10,0x10,0mm (max), Pitch 0,40mm, IPC High Density"
  rect 5.1x5.1 smd paste-3: 0(0,0)
  rect 0.75x0.25 smd: 1(-4.875,4) 2(-4.875,3.6) 3(-4.875,3.2) 4(-4.875,2.8) 5(-4.875,2.4) 6(-4.875,2) 7(-4.875,1.6) 8(-4.875,1.2) 9(-4.875,0.8) 10(-4.875,0.4) 11(-4.875,0) 12(-4.875,-0.4) 13(-4.875,-0.8) 14(-4.875,-1.2) 15(-4.875,-1.6) 16(-4.875,-2) 17(-4.875,-2.4) 18(-4.875,-2.8) 19(-4.875,-3.2) 20(-4.875,-3.6) 21(-4.875,-4) 43(4.875,-4) 44(4.875,-3.6) 45(4.875,-3.2) 46(4.875,-2.8) 47(4.875,-2.4) 48(4.875,-2) 49(4.875,-1.6) 50(4.875,-1.2) 51(4.875,-0.8) 52(4.875,-0.4) 53(4.875,0) 54(4.875,0.4) 55(4.875,0.8) 56(4.875,1.2) 57(4.875,1.6) 58(4.875,2) 59(4.875,2.4) 60(4.875,2.8) 61(4.875,3.2) 62(4.875,3.6) 63(4.875,4)
  rect 0.25x0.75 smd: 22(-4,-4.875) 23(-3.6,-4.875) 24(-3.2,-4.875) 25(-2.8,-4.875) 26(-2.4,-4.875) 27(-2,-4.875) 28(-1.6,-4.875) 29(-1.2,-4.875) 30(-0.8,-4.875) 31(-0.4,-4.875) 32(0,-4.875) 33(0.4,-4.875) 34(0.8,-4.875) 35(1.2,-4.875) 36(1.6,-4.875) 37(2,-4.875) 38(2.4,-4.875) 39(2.8,-4.875) 40(3.2,-4.875) 41(3.6,-4.875) 42(4,-4.875) 64(4,4.875) 65(3.6,4.875) 66(3.2,4.875) 67(2.8,4.875) 68(2.4,4.875) 69(2,4.875) 70(1.6,4.875) 71(1.2,4.875) 72(0.8,4.875) 73(0.4,4.875) 74(0,4.875) 75(-0.4,4.875) 76(-0.8,4.875) 77(-1.2,4.875) 78(-1.6,4.875) 79(-2,4.875) 80(-2.4,4.875) 81(-2.8,4.875) 82(-3.2,4.875) 83(-3.6,4.875) 84(-4,4.875)
  silkscreen extent -5.92,-5 5,5, body extent -5,-5 5,5, height 0.85
QFP-10020X14/0.65] [mm] "Thin QFP, 100-Leads, Body 20x14mm, Pitch 0.65mm, IPC Medium Density"
  oval 1.75x0.4 smd mask+0.075: 1(-7.625,9.425) 2(-7.625,8.775) 3(-7.625,8.125) 4(-7.625,7.475) 5(-7.625,6.825) 6(-7.625,6.175) 7(-7.625,5.525) 8(-7.625,4.875) 9(-7.625,4.225) 10(-7.625,3.575) 11(-7.625,2.925) 12(-7.625,2.275) 13(-7.625,1.625) 14(-7.625,0.975) 15(-7.625,0.325) 16(-7.625,-0.325) 17(-7.625,-0.975) 18(-7.625,-1.625) 19(-7.625,-2.275) 20(-7.625,-2.925) 21(-7.625,-3.575) 22(-7.625,-4.225) 23(-7.625,-4.875) 24(-7.625,-5.525) 25(-7.625,-6.175) 26(-7.625,-6.825) 27(-7.625,-7.475) 28(-7.625,-8.125) 29(-7.625,-8.775) 30(-7.625,-9.425) 51(7.625,-9.425) 52(7.625,-8.775) 53(7.625,-8.125) 54(7.625,-7.475) 55(7.625,-6.825) 56(7.625,-6.175) 57(7.625,-5.525) 58(7.625,-4.875) 59(7.625,-4.225) 60(7.625,-3.575) 61(7.625,-2.925) 62(7.625,-2.275) 63(7.625,-1.625) 64(7.625,-0.975) 65(7.625,-0.325) 66(7.625,0.325) 67(7.625,0.975) 68(7.625,1.625) 69(7.625,2.275) 70(7.625,2.925) 71(7.625,3.575) 72(7.625,4.225) 73(7.625,4.875) 74(7.625,5.525) 75(7.625,6.175) 76(7.625,6.825) 77(7.625,7.475) 78(7.625,8.125) 79(7.625,8.775) 80(7.625,9.425)
  oval 0.4x1.75 smd mask+0.075: 31(-6.175,-10.625) 32(-5.525,-10.625) 33(-4.875,-10.625) 34(-4.225,-10.625) 35(-3.575,-10.625) 36(-2.925,-10.625) 37(-2.275,-10.625) 38(-1.625,-10.625) 39(-0.975,-10.625) 40(-0.325,-10.625) 41(0.325,-10.625) 42(0.975,-10.625) 43(1.625,-10.625) 44(2.275,-10.625) 45(2.925,-10.625) 46(3.575,-10.625) 47(4.225,-10.625) 48(4.875,-10.625) 49(5.525,-10.625) 50(6.175,-10.625) 81(6.175,10.625) 82(5.525,10.625) 83(4.875,10.625) 84(4.225,10.625) 85(3.575,10.625) 86(2.925,10.625) 87(2.275,10.625) 88(1.625,10.625) 89(0.975,10.625) 90(0.325,10.625) 91(-0.325,10.625) 92(-0.975,10.625) 93(-1.625,10.625) 94(-2.275,10.625) 95(-2.925,10.625) 96(-3.575,10.625) 97(-4.225,10.625) 98(-4.875,10.625) 99(-5.525,10.625) 100(-6.175,10.625)
  silkscreen extent -7.75,-9.35 6.35,10.33, body extent -7,-10 7,10, height 1.6
R0603-PHILLIPS [mm]
  rect 0.8x0.8 smd: 1(-0.75,0) 2(0.75,0)
  silkscreen extent -1.45,-0.69 1.45,0.69, body extent -0.86,-0.45 0.85,0.45, height 0.9
RF-MCX [mm]
  round 2 hole 1.3: 1(0,0)
  round 2 hole 1.4: 2(-2.54,-2.54) 2(-2.54,2.54) 2(2.54,-2.54) 2(2.54,2.54)
  silkscreen extent -3.1,-3.1 3.1,3.1, body extent -2.97,-2.95 2.98,3, height 5.5
SLP2x2 [mm] "MGA-6338 Avago"
  rect 0.8x2 smd paste-0.5: 0(0,0)
  rect 0.45x0.25 smd paste-0.02 mask+0.075: 1(-0.875,0.75) 2(-0.875,0.25) 3(-0.875,-0.25) 4(-0.875,-0.75) 5(0.875,-0.75) 6(0.875,-0.25) 7(0.875,0.25) 8(0.875,0.75)
  rect 0.56x0.21 on Top Paste paste-0.5: ""(0,0.5) ""(0,0) ""(0,-0.5)
  rect 0.9x0.3 on Top Solder paste-0.5: ""(0,0.5) ""(0,0) ""(0,-0.5)
  silkscreen extent -1.6,-1.1 1,1.1, body extent -1,-1 1,1, height 0.8
SMC [mil]
  rect 100x160 smd: 1(-135,0) 2(135,0)
  silkscreen extent -140,-120 140,120, body extent -156,-117 156,115, height 91
SO-8 [mil] "R-PDSO-G8"
  rect 80x25 smd: 1(-110.12,74.8)
  oval 80x25 smd: 2(-109.88,25) 3(-109.88,-25) 4(-109.88,-75) 5(110.12,-75) 6(110.12,-25) 7(110.12,25) 8(110.12,75)
  silkscreen extent -56,-105 54,105, body extent -114,-96 114,97, height 57
SO-8-MICRO [mm]
  rect 0.4x1.4 smd mask+0.075: 1(-0.975,-2.2) 2(-0.325,-2.2) 3(0.325,-2.2) 4(0.975,-2.2) 5(0.975,2.2) 6(0.325,2.2) 7(-0.325,2.2) 8(-0.975,2.2)
  silkscreen extent -1.65,-1.65 1.65,1.65, body extent -1.5,-2.45 1.5,2.45, height 0.85
SOIC8 [mm]
  rect 1.27x0.64 smd: 1(-2.605,1.905) 2(-2.605,0.635) 3(-2.605,-0.635) 4(-2.605,-1.905) 5(2.605,-1.905) 6(2.605,-0.635) 7(2.605,0.635) 8(2.605,1.905)
  silkscreen extent -1.52,-2.6 1.52,2.54, body extent -2.84,-2.4 2.94,2.5, height 1.45
"SOIC8 - BackGND - 0.4mm dia" [mm]
  round 0.5 hole 0.4 paste+0.05: 0(-0.919,2.342) 0(-0.919,-0.325) 0(-0.919,1.072) 0(-0.919,-1.595) 0(-0.003,-2.298) 0(0.013,1.707) 0(0.013,0.31) 0(0.013,-0.96) 0(0.878,2.342) 0(0.878,-0.325) 0(0.878,1.072) 0(0.878,-1.595)
  rect 2.67x5.6 smd paste-2: 0(-0.003,0.002)
  rect 2.67x5.6 smd far side paste-2: 0(-0.003,0.002)
  rect 1.27x0.64 smd: 1(-2.608,1.907) 2(-2.608,0.637) 3(-2.608,-0.633) 4(-2.608,-1.903) 5(2.602,-1.903) 6(2.602,-0.633) 7(2.602,0.637) 8(2.602,1.907)
  rect 2.67x3.3 on Top Solder: ""(-0.003,0.002)
  rect 2.67x3.3 on Top Paste: ""(0,0)
  silkscreen extent -1.65,-2.54 1.65,2.54, body extent -2.84,-2.45 2.94,2.45, height 1.45
SOT23-Philips [mm]
  rect 0.6x0.7 smd: 1(-0.95,-1) 2(0.95,-1) 3(0,1)
  silkscreen extent -1.52,0 1.52,1.27, body extent -1.46,-1.25 1.46,1.23, height 1
SOT-23-5[3.1x1.8/0.95] [mm] "SOT-25"
  rect 0.6x1.27 smd: 1(-0.949,-1.385) 2(0.001,-1.385) 3(0.951,-1.385) 4(0.951,1.409) 5(-0.949,1.409)
  silkscreen extent -1.52,-2.27 1.52,2.3, body extent -1.65,-1.5 1.65,1.5, height 1.04
SOT-23-6 [mm]
  rect 0.6x1.27 smd: 1(-0.951,-1.385) 2(0,-1.385) 3(0.951,-1.385) 4(0.951,1.385) 5(0,1.385) 6(-0.951,1.385)
  silkscreen extent -1.52,-2.27 1.52,2.3, body extent -1.65,-1.5 1.65,1.5, height 1.09
SOT-223 [mm]
  rect 1.5x2 smd: 1(-2.3,-3.15) 2(0,-3.15) 3(2.3,-3.15)
  rect 3.8x2 smd: 4(0,3.15)
  silkscreen extent -3.94,-1.4 3.94,3.04, body extent -3.25,-3.35 3.25,3.55, height 1.6
SOT-223-1 [mm] "SOT223 с другой нумерацией пинов"
  rect 1.5x2 smd: 1(0,0) 2(2.3,0) 3(4.6,0)
  rect 3.8x2 smd: 2(2.3,6.3)
  silkscreen extent -1.64,1.75 6.24,6.19, body extent -0.95,-0.2 5.55,6.7, height 1.6
SSOP-28(5.3x10/0.65) [mm]
  rect 1.6x0.4 smd mask+0.075: 1(-3.55,4.225) 2(-3.55,3.575) 3(-3.55,2.925) 4(-3.55,2.275) 5(-3.55,1.625) 6(-3.55,0.975) 7(-3.55,0.325) 8(-3.55,-0.325) 9(-3.55,-0.975) 10(-3.55,-1.625) 11(-3.55,-2.275) 12(-3.55,-2.925) 13(-3.55,-3.575) 14(-3.55,-4.225) 15(3.55,-4.225) 16(3.55,-3.575) 17(3.55,-2.925) 18(3.55,-2.275) 19(3.55,-1.625) 20(3.55,-0.975) 21(3.55,-0.325) 22(3.55,0.325) 23(3.55,0.975) 24(3.55,1.625) 25(3.55,2.275) 26(3.55,2.925) 27(3.55,3.575) 28(3.55,4.225)
  silkscreen extent -2.3,-5 2.3,5, body extent -3.95,-4.85 3.95,4.85, height 1.87
TCXO7X5 [mil]
  rect 70x80 smd: 1(0,0) 2(250,0) 3(250,140) 4(0,140)
  silkscreen extent -24,-39 272,173, body extent -16,-31 264,169, height 59
TF160808-Phillips [mm]
  rect 0.8x0.8 smd: 1(-0.75,0) 2(0.75,0)
  silkscreen extent -1.45,-0.69 1.45,0.69, body extent -0.86,-0.45 0.85,0.45, height 0.9
TI2012-Phillips [mm]
  rect 0.9x1.3 smd: 1(-1.15,0) 2(1.15,0)
  silkscreen extent -1.91,-0.92 1.91,0.92, body extent -1.32,-0.69 1.23,0.67, height 1
TI160808-PHILLIPS [mm]
  rect 0.8x0.8 smd: 1(-0.75,0) 2(0.75,0)
  silkscreen extent -1.45,-0.69 1.45,0.69, body extent -0.86,-0.45 0.85,0.45, height 0.9
Ti160808-Phillips [mm]
  rect 0.8x0.8 smd: 1(-0.75,0) 2(0.75,0)
  silkscreen extent -1.45,-0.69 1.45,0.69, body extent -0.86,-0.45 0.85,0.45, height 0.9
to-252 [mm]
  rect 1.3x1.7 smd: 1(0,0) 3(4.57,0)
  rect 5.6x5.8 smd: 2(2.285,7.4)
  silkscreen extent -1.3,-1.4 5.87,10.9, body extent -1,0.2 5.6,10.3, height 2.4
USB/SM0.8-6H5 [mm] "Connector; USB2.0, Type B, SM; 5 Position; Right Angle"
  rect 3.5x2 smd: 0(-7.55,-4.45) 0(-7.55,4.45)
  rect 4x2 smd: 0(-3.3,4.45) 0(-3.3,-4.45)
  rect 2.3x0.5 smd: 1(-7.85,-1.6) 2(-7.85,-0.8) 3(-7.85,0) 4(-7.85,1.6) x(-7.85,0.8)
  round 0.6 hole 0.9 unplated: MH1(-5.2,2.2) MH2(-5.25,-2.2)
  silkscreen extent -9.68,-4.95 0.7,4.95, body extent -8.35,-5 0.65,4.9, height 3.9
WF-2 [mil] "DC Power Connector"
  rect 60x60 hole 44: 1(0,0)
  round 60 hole 44: 2(100,0)
  silkscreen extent -58,-127 157,120, body extent -49,-118 148,110, height 461
YC248 [mm] "Резисторная сборка 8х0.5мм"
  rect 0.7x0.3 smd: 1(-0.65,1.75) 2(-0.65,1.25) 3(-0.65,0.75) 4(-0.65,0.25) 5(-0.65,-0.25) 6(-0.65,-0.75) 7(-0.65,-1.25) 8(-0.65,-1.75) 9(0.65,-1.75) 10(0.65,-1.25) 11(0.65,-0.75) 12(0.65,-0.25) 13(0.65,0.25) 14(0.65,0.75) 15(0.65,1.25) 16(0.65,1.75)
  silkscreen extent -1.57,-2.17 0.9,2.52, body extent -0.82,-1.9 0.77,1.9, height 0.45

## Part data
C1 C2 C4 C5 C7 C8 C10 C11 C13 C14 C15 C18 C20 C21 C22 C24 C25 C26 C27 C28 C29 C30 C31 C33 C34 C35 C36 C37 C39 C40 C42 C43 C44-1 C44-2 C46-1 C46-2 C47-1 C47-2 C48-1 C48-2 C49-1 C49-2 C50-1 C50-2 C55-1 C55-2 C56-1 C56-2 C57-1 C57-2 C58-1 C58-2 C59-1 C59-2 C60-1 C60-2 C61-1 C61-2 C62-1 C62-2 C63-1 C63-2 C69-1 C69-2 C70-1 C70-2 C71-1 C71-2 C72-1 C72-2 C78-1 C78-2 C79-1 C79-2 C80-1 C80-2 C85-1 C85-2 C86-1 C86-2 C87-1 C87-2 C88-1 C88-2 C89-1 C89-2 C90-1 C90-2 C91-1 C91-2 C92-1 C92-2 C93-1 C93-2 C94-1 C94-2 C113 C127 C135 C139 C143 C144 C145 C147 C148 C149 C155 C156 C157 C158 C159 C160 C172 C174 C175 C176 C177 C178 C179 C180 C181 C182 C183 C184 C185 C186 C187 C188 C189 C190 C191 C192 C193 C194 C196 C197 C198 C199 C200 C201 C202 C203 C204 C205 C206 C207 C208 C209 C210 C211 C212 C213 C214 C215 C216 C217 C218 C219 C220 C221 C222 C223 C224 C225 C226 C227 C228 C229 C230 C231 C232 C233 C234 C235 C236 C237 C238 C239 C240 C241 C242 C243 C244 C245 C246 C247 C248 C249 C250 C251 C252 C254 C255 C256 C257 C258 C259 C260 C262 C263 C264 C265 C268 C270 C271 C272 C273 C274 C275 C276 C277 C278 C279 C280 C281 C282 C286 C287 C288 C289 C292 C293 C294 C295 C296 C297 C298 C299 C306 C308 C312 C313 C314 C315: library part C0402, "Конденсатор"
C6 C17 C38 C51-1 C51-2 C52-1 C52-2 C53-1 C53-2 C54-1 C54-2 C125 C146 C165 C166 C167 C168 C171: library part CD7343, "Конденсатор"
C12 C64-1 C64-2 C65-1 C65-2 C66-1 C66-2 C67-1 C67-2 C169: library part CA3216, "Конденсатор"
C19 C32 C41 C45-1 C45-2 C68-1 C68-2 C73-1 C73-2 C74-1 C74-2 C75-1 C75-2 C76-1 C76-2 C77-1 C77-2 C81-1 C81-2 C82-1 C82-2 C83-1 C83-2 C84-1 C84-2 C95-1 C95-2 C96-1 C96-2 C97-1 C97-2 C98-1 C98-2 C99-1 C99-2 C100-1 C100-2 C101-1 C101-2 C102-1 C102-2 C103-1 C103-2 C104-1 C104-2 C105-1 C105-2 C106-1 C106-2 C107-1 C107-2 C108-1 C108-2 C109-1 C109-2 C110-1 C110-2 C111-1 C111-2 C112-1 C112-2 C128 C129 C130 C132 C133 C134 C150 C151 C152 C153 C154 C161 C162 C163 C164 C170 C266 C267 C269 C300 C301 C302 C303 C304 C305 C307 C309 C310 C311 C316 C318 C319: library part C0603, "Конденсатор"
C114 C115 C116 C117 C131 C140 C141 C142: library part CASE-G, "Конденсатор"
C118 C119 C120 C121 C122 C123 C124 C126 C136 C137 C138 C261: library part C1206, "Конденсатор"
C283 C284 C285: library part C0805, "Конденсатор"
C317: library part CB3528, "Конденсатор"
D1 D2 D3 D4 D5: "Диод"
J1: library part JUMP-2, "Перемычка"
L1 L2 L3 L4 L5 L6-1 L6-2 L7-1 L7-2 L8-1 L8-2 L9-1 L9-2 L10-1 L10-2 L11-1 L11-2 L12-1 L12-2 L13-1 L13-2 L14-1 L14-2 L15-1 L15-2 L16-1 L16-2 L17-1 L17-2 L18-1 L18-2 L19-1 L19-2 L20-1 L20-2 L21-1 L21-2 L22-1 L22-2 L23-1 L23-2 L24-1 L24-2 L25-1 L25-2 L26-1 L26-2 L27-1 L27-2 L28-1 L28-2 L29-1 L29-2 L45 L46 L47 L48 L49 L50 L55: library part TI160808, "Дроссель ЭМС"
L30-1 L30-2 L31-1 L31-2 L32-1 L32-2 L33-1 L33-2 L51 L52 L53 L54: library part TF160808, "Индуктивность"
L34 L40 L41 L42 L43: library part TI2012_1, "Дроссель ЭМС"
L35 L36 L37 L38: library part DS3316P, "Дроссель"
L39 L44: library part L-1812, "Индуктивность"
LED1 LED2 LED3: library part L7104SA/3, "Светодиод"
LED4: "Светодиод"
LED5 LED6: library part LED0603, "Светодиод"
Q1 Q2 Q3: "Транзистор"
Q4: library part "BC 817", "Транзистор"
R1 R2 R3 R4 R5 R6 R7 R8 R9 R10 R11 R12 R13 R14 R15 R16 R17 R18 R19 R20 R21 R22 R23 R24 R25 R26 R27 R28 R29 R30 R31 R32 R33 R34 R35 R36 R37 R38 R39 R40 R41 R42 R43 R44 R45 R46 R47 R48 R49 R50 R51 R52 R53 R54 R55 R56 R57 R58 R59 R60 R61 R62 R63 R64 R65 R66 R67 R78 R90 R91 R92 R93 R94 R95-1 R95-2 R96-1 R96-2 R97-1 R97-2 R98-1 R98-2 R99-1 R99-2 R100-1 R100-2 R101-1 R101-2 R102-1 R102-2 R103-1 R103-2 R104-1 R104-2 R105-1 R105-2 R106-1 R106-2 R107-1 R107-2 R108-1 R108-2 R109-1 R109-2 R110-1 R110-2 R111-1 R111-2 R112-1 R112-2 R113-1 R113-2 R114-1 R114-2 R115-1 R115-2 R116-1 R116-2 R117-1 R117-2 R118-1 R118-2 R119-1 R119-2 R120-1 R120-2 R121-1 R121-2 R122-1 R122-2 R123-1 R123-2 R124-1 R124-2 R125-1 R125-2 R126-1 R126-2 R127-1 R127-2 R128 R129 R130 R131 R132 R133 R134 R135 R136 R137 R138 R139 R140 R141 R142 R143 R144 R145 R146 R147 R148 R149 R150 R151 R152 R153 R154-1 R154-2 R155-1 R155-2 R156-1 R156-2 R157-1 R157-2 R158-1 R158-2 R159-1 R159-2 R160 R161 R162 R163 R164 R165 R166 R167 R168 R169 R170 R171 R172 R173 R174: library part R0603, "Резистор"
RA1 RA2 RA3: library part YC248, "Резисторная сборка"
SW1 SW2: library part KNOPKA, "Кнопка"
SW3 SW4: library part JUMP-3, "Перемычка"
T1-1 T1-2 T2-1 T2-2: library part TC1-1-13, "Трансформатор"
T3-1 T3-2: library part TC4-25, "Трансформатор"
T4 T5: library part SBTC-2-10L, "Трансформатор"
U1 U9 U11 U12-1 U12-2 U21 U23 U24 U25 U33 U35: "Микросхема"
U2: library part OCVCXO, "OCVCXO"
U3: library part TCVCXO_5X3, "TCVCXO"
U4: "Модуль"
U5: library part SI5330, "Микросхема"
U6: library part M25P40-VMN6T, "Микросхема"
U7: library part AT24CXX, "Микросхема"
U8: "Spartan-6 LX 1.2V FPGA, 270 User I/Os, 484-Ball Fine-Pitch BGA (1.0mm Pitch), Speed Grade 2, Commercial Grade, Pb-Free"
U10: "Генератор"
U13-1 U13-2 U14-1 U14-2: library part AD8130, "Микросхема"
U15 U16 U17 U34: library part L5973D, "Микросхема"
U18 U28 U30-1 U30-2 U31-1 U31-2 U32-1 U32-2: library part LD1117ADJ, "Микросхема"
U19: library part TPS6040x, "Микросхема"
U20 U22 U26 U27: library part 74LVC2T45DCT, "Микросхема"
U29-1 U29-2: library part LD1117FIX, "Микросхема"
X1 X2 X5 X12 X26: "Разъем"
X3: library part "USB M-1J", "Разъём"
X4: library part "RJ45 0826-1XT-23-F", "Модуль разъёма"
X6 X7 X8 X9 X10 X11: library part "MCX SM"
X12-1 X12-2 X13-1 X13-2 X14-1 X14-2 X15-1 X15-2 X16-1 X16-2 X17-1 X17-2 X18 X19 X20 X21 X22 X23 X24 X25: library part KP, "Контактная площадка"
X27 X28: library part WF-2, "Разъем"
Z1-1 Z1-2: library part NFM3DP, "Фильтр"
Z2 Z3: library part "SAW 3x3 SMD", "Фильтр ПАВ"

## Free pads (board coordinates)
  rect 4x4 hole 2.8 paste-3: 0(2.5,110.5) 0(2.5,2.5) 0(86,2.5) 0(86,110.5) 0(169.5,2.5) 0(169.5,110.5)

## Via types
v1: diameter 0.45, hole 0.2, Top Layer to Bottom Layer, tented both sides, 554 vias
v2: diameter 0.5, hole 0.2, Top Layer to Bottom Layer, tented both sides, 468 vias
v3: diameter 0.7, hole 0.3, Top Layer to Bottom Layer, tented both sides, 206 vias
v4: diameter 0.4, hole 0.2, Top Layer to Bottom Layer, tented both sides, 82 vias
v5: diameter 0.8, hole 0.3, Top Layer to Bottom Layer, tented both sides, 16 vias
v6: diameter 0.6, hole 0.25, Top Layer to Bottom Layer, tented both sides, 16 vias
v7: diameter 0.5, hole 0.3, Top Layer to Bottom Layer, tented both sides, 8 vias
v8: diameter 0.7, hole 0.3, Top Layer to Bottom Layer, 4 vias
v9: diameter 0.6, hole 0.3, Top Layer to Bottom Layer, tented both sides, 4 vias
v10: diameter 0.5, hole 0.2, Top Layer to Bottom Layer, 2 vias

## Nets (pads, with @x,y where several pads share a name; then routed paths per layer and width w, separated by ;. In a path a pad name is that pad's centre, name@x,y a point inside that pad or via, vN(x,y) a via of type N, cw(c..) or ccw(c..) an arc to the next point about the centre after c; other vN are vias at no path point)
+1,2VFPGA: C138.1 C142.1 C148.1 C154.1 C260.1 C262.1 C263.1 C264.1 C265.1 C268.1 C270.1 C271.1 C272.1 C273.1 C274.1 C276.1 C277.1 L38.1 R138.1 U8.J8 U8.J10 U8.J12 U8.J14 U8.K9 U8.K11 U8.K13 U8.L10 U8.L12 U8.L14 U8.M9 U8.M11 U8.M13 U8.N10 U8.N12 U8.N14 U8.P9 U8.P11 U8.P13 U8.R14 | length 53.8
  Top Layer w0.2: C154.1@39.9,81.75 39.95,81.8 v3(40.6,81.8) C148.1@41.2,81.8 ; C148.1@41.15,81.75 C148.1@41.2,81.8 ; R138.1@41.15,83 41.2,82.95 C148.1@41.2,81.8 ; U8.J14@63,44 v1(63.5,43.5) ; U8.L14@63,46 v1(63.5,45.5) U8.K13@64,45 ; U8.N14@63,48 v1(63.5,47.5) U8.M13@64,47 ; U8.R14@63,50 v1(63.5,49.5) ; v1@63.35,43.5 ccw(c62.988,43.5) 63.244,43.756 ccw(c63.5,44.012) v1@63.5,43.65 ; v1@63.35,45.5 ccw(c62.988,45.5) 63.244,45.756 ccw(c63.5,46.012) v1@63.5,45.65 ; v1@63.35,47.5 ccw(c62.988,47.5) 63.244,47.756 ccw(c63.5,48.012) v1@63.5,47.65 ; v1@63.35,49.5 ccw(c62.988,49.5) 63.244,49.756 ccw(c63.5,50.012) v1@63.5,49.65 ; v1@63.5,45.35 cw(c63.5,44.988) 63.756,45.244 cw(c64.012,45.5) v1@63.65,45.5 ; v1@63.5,47.35 cw(c63.5,46.988) 63.756,47.244 cw(c64.012,47.5) v1@63.65,47.5 ; U8.P13@64,49 v1(64.5,48.5) U8.N12@65,48 ; v1@64.35,48.5 ccw(c63.988,48.5) 64.244,48.756 ccw(c64.5,49.012) v1@64.5,48.65 ; v1@64.5,44.35 cw(c64.5,43.988) 64.756,44.244 cw(c65.012,44.5) v1@64.65,44.5 ; v1(64.5,44.5) U8.J12@65,44 ; v1@64.5,48.35 cw(c64.5,47.988) 64.756,48.244 cw(c65.012,48.5) v1@64.65,48.5 ; U8.L12@65,46 v1(65.5,45.5) U8.K11@66,45 ; v1@65.35,45.5 ccw(c64.988,45.5) 65.244,45.756 ccw(c65.5,46.012) v1@65.5,45.65 ; v1@65.5,45.35 cw(c65.5,44.988) 65.756,45.244 cw(c66.012,45.5) v1@65.65,45.5 ; U8.M11@66,47 v1(66.5,46.5) U8.L10@67,46 ; U8.P11@66,49 v1(66.5,48.5) U8.N10@67,48 ; v1@66.35,46.5 ccw(c65.988,46.5) 66.244,46.756 ccw(c66.5,47.012) v1@66.5,46.65 ; v1@66.35,48.5 ccw(c65.988,48.5) 66.244,48.756 ccw(c66.5,49.012) v1@66.5,48.65 ; v1@66.5,44.35 cw(c66.5,43.988) 66.756,44.244 cw(c67.012,44.5) v1@66.65,44.5 ; v1(66.5,44.5) U8.J10@67,44 ; v1@66.5,46.35 cw(c66.5,45.988) 66.756,46.244 cw(c67.012,46.5) v1@66.65,46.5 ; v1@66.5,48.35 cw(c66.5,47.988) 66.756,48.244 cw(c67.012,48.5) v1@66.65,48.5 ; v1@67.5,47.35 cw(c67.5,46.988) 67.756,47.244 cw(c68.012,47.5) v1@67.65,47.5 ; v1(67.5,47.5) U8.M9@68,47 ; U8.K9@68,45 v1(68.5,44.5) U8.J8@69,44 ; U8.P9@68,49 v1(68.5,49.5) ; v1@68.35,44.5 ccw(c67.988,44.5) 68.244,44.756 ccw(c68.5,45.012) v1@68.5,44.65 ; v1@68.35,49.5 cw(c67.988,49.5) 68.244,49.244 cw(c68.5,48.988) v1@68.5,49.35 ; v1@68.5,44.35 cw(c68.5,43.988) 68.756,44.244 cw(c69.012,44.5) v1@68.65,44.5
  Top Layer w0.5: C142.1@34.35,81.4 34.7,81.75 C138.1@37.9,81.75 ; 36.238,81.75 ccw(c36.238,82.162) v3@36.529,81.871 ; v3@36.671,81.871 ccw(c36.962,82.162) 36.962,81.75 ; L38.1@37.55,84.3 37.9,83.95 v3(37.9,82.5) C138.1@37.9,81.75 ; C138.1@37.9,81.7 C138.1@37.9,81.75 ; C154.1@39.9,81.75 v3(39.05,81.75) C138.1@37.9,81.75
  Bottom Layer w0.2: C273.1@63,46 v1(63.5,45.5) ; C263.1@63,47 v1(63.5,47.5) ; C265.1@63,49 v1(63.5,49.5) ; v1@63.35,45.5 ccw(c62.988,45.5) 63.244,45.756 ccw(c63.5,46.012) v1@63.5,45.65 ; v1@63.35,47.5 cw(c62.988,47.5) 63.244,47.244 cw(c63.5,46.988) v1@63.5,47.35 ; v1@63.35,49.5 cw(c62.988,49.5) 63.244,49.244 cw(c63.5,48.988) v1@63.5,49.35 ; v1(63.5,43.5) C262.1@64,44 ; v1@63.5,43.65 ccw(c63.5,44.012) 63.756,43.756 ccw(c64.012,43.5) v1@63.65,43.5 ; C274.1@64,45 v1(64.5,44.5) ; C277.1@64,48 v1(64.5,48.5) ; v1@64.35,44.5 ccw(c63.988,44.5) 64.244,44.756 ccw(c64.5,45.012) v1@64.5,44.65 ; v1@64.35,48.5 cw(c63.988,48.5) 64.244,48.244 cw(c64.5,47.988) v1@64.5,48.35 ; C264.1@65,46 v1(65.5,45.5) ; v1@65.35,45.5 ccw(c64.988,45.5) 65.244,45.756 ccw(c65.5,46.012) v1@65.5,45.65 ; C270.1@66,47 v1(66.5,46.5) ; v1@66.35,46.5 ccw(c65.988,46.5) 66.244,46.756 ccw(c66.5,47.012) v1@66.5,46.65 ; v1(66.5,44.5) C272.1@67,45 ; v1@66.5,44.65 ccw(c66.5,45.012) 66.756,44.756 ccw(c67.012,44.5) v1@66.65,44.5 ; v1@66.5,48.35 cw(c66.5,47.988) 66.756,48.244 cw(c67.012,48.5) v1@66.65,48.5 ; v1(66.5,48.5) C268.1@67,48 ; v1@67.5,47.35 cw(c67.5,46.988) 67.756,47.244 cw(c68.012,47.5) v1@67.65,47.5 ; v1(67.5,47.5) C276.1@68,47 ; C271.1@68,49 v1(68.5,49.5) ; v1@68.35,49.5 cw(c67.988,49.5) 68.244,49.244 cw(c68.5,48.988) v1@68.5,49.35 ; v1(68.5,44.5) C260.1@69,45 ; v1@68.5,44.65 ccw(c68.5,45.012) 68.756,44.756 ccw(c69.012,44.5) v1@68.65,44.5
  other v3: 36.6,81.8
+1,8VALMS-1: C67-1.1 C72-1.1 L14-1.1 L15-1.1 R101-1.2 U32-1.2 | length 59.9
  Top Layer w0.3: 145.351,35.806 C72-1.1@145.351,36.619 ; 145.668,35.806 145.697,35.777 146.512,35.777 R101-1.2@146.542,35.806
  Top Layer w0.5: v3(136.65,38.8) 141.75,38.8 143.15,37.4 C67-1.1@143.15,36.7 ; C67-1.1@143.7,36.6 144.5,35.8 144.506,35.806 145.351,35.806 145.668,35.806 R101-1.2@146.542,35.806 148.74,35.806 U32-1.2@148.74,36.156
  Top Layer w1: U32-1.2@148.74,36.156 U32-1.2@155.04,36.156 155.04,37.626 v3(156.915,39.502)
  Mid-Layer 2 w0.5: v1@129.55,27.858 130.423,27.858 130.444,27.838 ; v1(132.511,13.658) 132.398,13.658 130.444,15.612 130.444,27.838 ; v3(136.65,38.8) 134.25,38.8 131.895,36.445 131.895,29.289 130.444,27.838
  Bottom Layer w0.2: v1@129.323,27.77 cw(c129.109,27.556) 129.411,27.556 cw(c129.713,27.556) v1@129.499,27.77 ; L15-1.1@129.411,27.058 v1(129.411,27.858) ; L14-1.1@131.107,14.088 132.081,14.088 v1(132.511,13.658) ; v1@132.386,13.658 ccw(c132.084,13.658) 132.298,13.872 ccw(c132.511,14.085) v1@132.511,13.783
  other v3: 152.801,32.398 156.915,32.398 155.053,32.442 150.852,32.485 156.915,34.824 156.959,37.163 150.852,39.545 153.061,39.588 155.096,39.588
